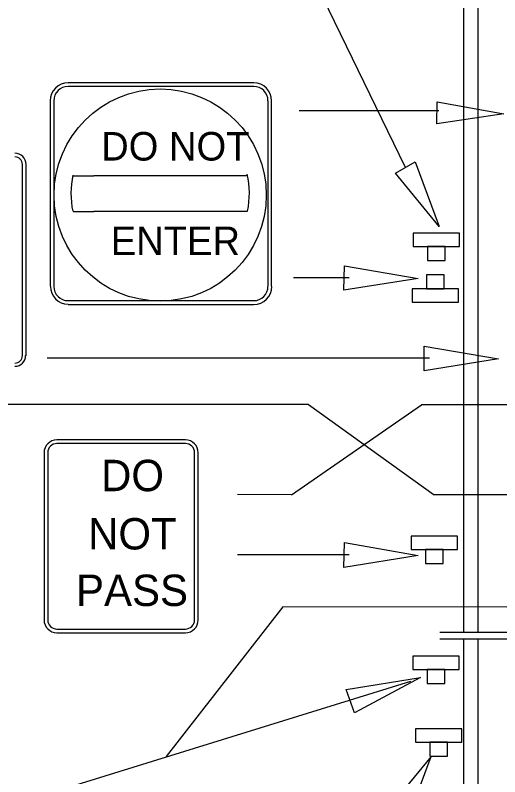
# Model space of a CAD drawing. Extents: x 1531.42 to 1538.58, y 1529.59 to 1539.57.
# Drawn here: x 1533.644 to 1534.775, y 1535.958 to 1537.736 of the extents above; entities that cross this region are included whole.
import ezdxf

# ---------------------------------------------------------------- set-up
doc = ezdxf.new("R2010")
doc.units = 0
doc.layers.add('DETL-DIMS', color=7, linetype='Continuous')
doc.layers.add('DETL-LINE', color=7, linetype='Continuous')

msp = doc.modelspace()

# ---------------------------------------------------------------- linework, layer by layer
at = {"layer": 'DETL-DIMS'}
for p, q in [((1534.5548, 1537.3801), (1534.3064, 1537.8927)), ((1534.6324, 1537.5122), (1534.3064, 1537.5122)), ((1534.4236, 1537.1229), (1534.2932, 1537.1229)), ((1534.6112, 1536.9353), (1533.7181, 1536.9353)), ((1534.3285, 1536.8269), (1532.8205, 1536.8278)), ((1534.2888, 1536.6165), (1534.5927, 1536.8261)), ((1534.3285, 1536.8269), (1534.6218, 1536.6165)), ((1534.7918, 1536.8261), (1534.5927, 1536.8261)), ((1534.2888, 1536.6165), (1534.1629, 1536.6173)), ((1534.7918, 1536.6165), (1534.6218, 1536.6165)), ((1534.4236, 1536.4764), (1534.1629, 1536.4764)), ((1534.2686, 1536.3549), (1533.9964, 1536.0052)), ((1534.7918, 1536.354), (1534.2686, 1536.3549)), ((1533.297, 1535.7885), (1534.5672, 1536.1813))]:
    msp.add_line(p, q, dxfattribs=at)
for points in [[(1534.6279, 1537.4823), (1534.6288, 1537.5334), (1534.7847, 1537.5052)], [(1534.5319, 1537.3669), (1534.5777, 1537.3933), (1534.6332, 1537.2427)], [(1534.4112, 1537.0939), (1534.4122, 1537.1511), (1534.5848, 1537.1211)], [(1534.5989, 1536.9053), (1534.5989, 1536.9635), (1534.7724, 1536.9335)], [(1534.4112, 1536.4465), (1534.4122, 1536.5046), (1534.5848, 1536.4746)], [(1534.4359, 1536.1073), (1534.4166, 1536.1619), (1534.5901, 1536.1901)], [(1534.5029, 1535.8695), (1534.5531, 1535.8405), (1534.6147, 1536.0052)]]:
    msp.add_lwpolyline(points, close=True, dxfattribs=at)
at = {"layer": 'DETL-LINE'}
for p, q in [((1534.6905, 1539.1347), (1534.6905, 1536.2958)), ((1534.724, 1539.1347), (1534.724, 1536.2958)), ((1534.2006, 1537.5779), (1533.7674, 1537.5779)), ((1534.2006, 1537.5695), (1533.7674, 1537.5695)), ((1533.7255, 1537.5361), (1533.7255, 1537.1029)), ((1533.734, 1537.5361), (1533.734, 1537.1029)), ((1534.234, 1537.1029), (1534.234, 1537.5361)), ((1534.2423, 1537.1029), (1534.2423, 1537.5361)), ((1533.6611, 1536.941), (1533.6611, 1537.3876)), ((1533.6691, 1536.941), (1533.6691, 1537.3876)), ((1533.7778, 1537.3611), (1533.8276, 1537.3611)), ((1534.1872, 1537.3611), (1533.8276, 1537.3611)), ((1533.779, 1537.2779), (1533.8276, 1537.2779)), ((1534.1858, 1537.2779), (1533.8276, 1537.2779)), ((1533.7674, 1537.0695), (1534.2006, 1537.0695)), ((1533.7674, 1537.0605), (1534.2006, 1537.0605)), ((1534.041, 1536.7444), (1533.7412, 1536.7444)), ((1534.041, 1536.7359), (1533.7412, 1536.7359)), ((1533.7111, 1536.7143), (1533.7111, 1536.3245)), ((1533.7196, 1536.7143), (1533.7196, 1536.3245)), ((1534.0626, 1536.3245), (1534.0626, 1536.7143)), ((1534.0711, 1536.3245), (1534.0711, 1536.7143)), ((1533.7412, 1536.3029), (1534.041, 1536.3029)), ((1533.7412, 1536.2944), (1534.041, 1536.2944)), ((1534.635, 1536.2958), (1534.9961, 1536.2958)), ((1534.635, 1536.28), (1534.9776, 1536.28)), ((1534.6905, 1536.28), (1534.6905, 1531.7597)), ((1534.724, 1536.28), (1534.724, 1531.7597))]:
    msp.add_line(p, q, dxfattribs=at)
for points in [[(1534.6812, 1537.1958), (1534.6812, 1537.2267), (1534.573, 1537.2267), (1534.573, 1537.1958)], [(1534.6476, 1537.1958), (1534.6063, 1537.1958), (1534.6063, 1537.163), (1534.6476, 1537.163)], [(1534.6041, 1537.0969), (1534.6454, 1537.0969), (1534.6454, 1537.1297), (1534.6041, 1537.1297)], [(1534.5705, 1537.0969), (1534.5705, 1537.066), (1534.6787, 1537.066), (1534.6787, 1537.0969)], [(1534.6767, 1536.4888), (1534.6767, 1536.5197), (1534.5685, 1536.5197), (1534.5685, 1536.4888)], [(1534.6431, 1536.4888), (1534.6018, 1536.4888), (1534.6018, 1536.456), (1534.6431, 1536.456)], [(1534.6801, 1536.2084), (1534.6801, 1536.2393), (1534.5719, 1536.2393), (1534.5719, 1536.2084)], [(1534.6465, 1536.2084), (1534.6052, 1536.2084), (1534.6052, 1536.1757), (1534.6465, 1536.1757)], [(1534.6868, 1536.0388), (1534.6868, 1536.0697), (1534.5786, 1536.0697), (1534.5786, 1536.0388)], [(1534.6532, 1536.0388), (1534.6119, 1536.0388), (1534.6119, 1536.0061), (1534.6532, 1536.0061)]]:
    msp.add_lwpolyline(points, close=True, dxfattribs=at)
msp.add_circle((1533.9822, 1537.3159), 0.2476, dxfattribs=at)
for centre, radius, start, end in [((1533.7673, 1537.5361), 0.0418, 90, 180), ((1533.7673, 1537.5361), 0.0333, 90, 180), ((1534.2006, 1537.5361), 0.0417, 0, 90), ((1534.2006, 1537.5361), 0.0333, 0, 90), ((1533.6431, 1537.3875), 0.026, 0, 90), ((1533.6431, 1537.3875), 0.0176, 0, 90), ((1533.9822, 1537.3199), 0.2083, 168.1886, 191.4966), ((1533.9822, 1537.3199), 0.2083, 348.5257, 12.4096), ((1533.7673, 1537.1028), 0.0414, 180, 270), ((1533.7673, 1537.1028), 0.0333, 180, 270), ((1534.2006, 1537.1028), 0.0333, 270, 0), ((1534.2006, 1537.1028), 0.0423, 270, 0), ((1533.6431, 1536.9414), 0.0176, 270, 0), ((1533.6431, 1536.9414), 0.025, 270, 0), ((1533.7411, 1536.7144), 0.03, 90, 180), ((1533.7411, 1536.7144), 0.0215, 90, 180), ((1534.0411, 1536.7144), 0.03, 0, 90), ((1534.0411, 1536.7144), 0.0215, 0, 90), ((1533.7411, 1536.3244), 0.03, 180, 270), ((1533.7411, 1536.3244), 0.0215, 180, 270), ((1534.0411, 1536.3244), 0.03, 270, 0), ((1534.0411, 1536.3244), 0.0215, 270, 0)]:
    msp.add_arc(centre, radius, start, end, dxfattribs=at)

# ---------------------------------------------------------------- texts
for s, height, p in [('DO NOT', 0.0666, (1533.8444, 1537.3965)), ('ENTER', 0.0666, (1533.8668, 1537.1757)), ('DO', 0.07326, (1533.8442, 1536.6247)), ('NOT', 0.07326, (1533.8139, 1536.4887)), ('PASS', 0.07326, (1533.7858, 1536.3567))]:
    msp.add_text(s, height=height, dxfattribs=at).set_placement(p)

doc.saveas('drawing.dxf')
